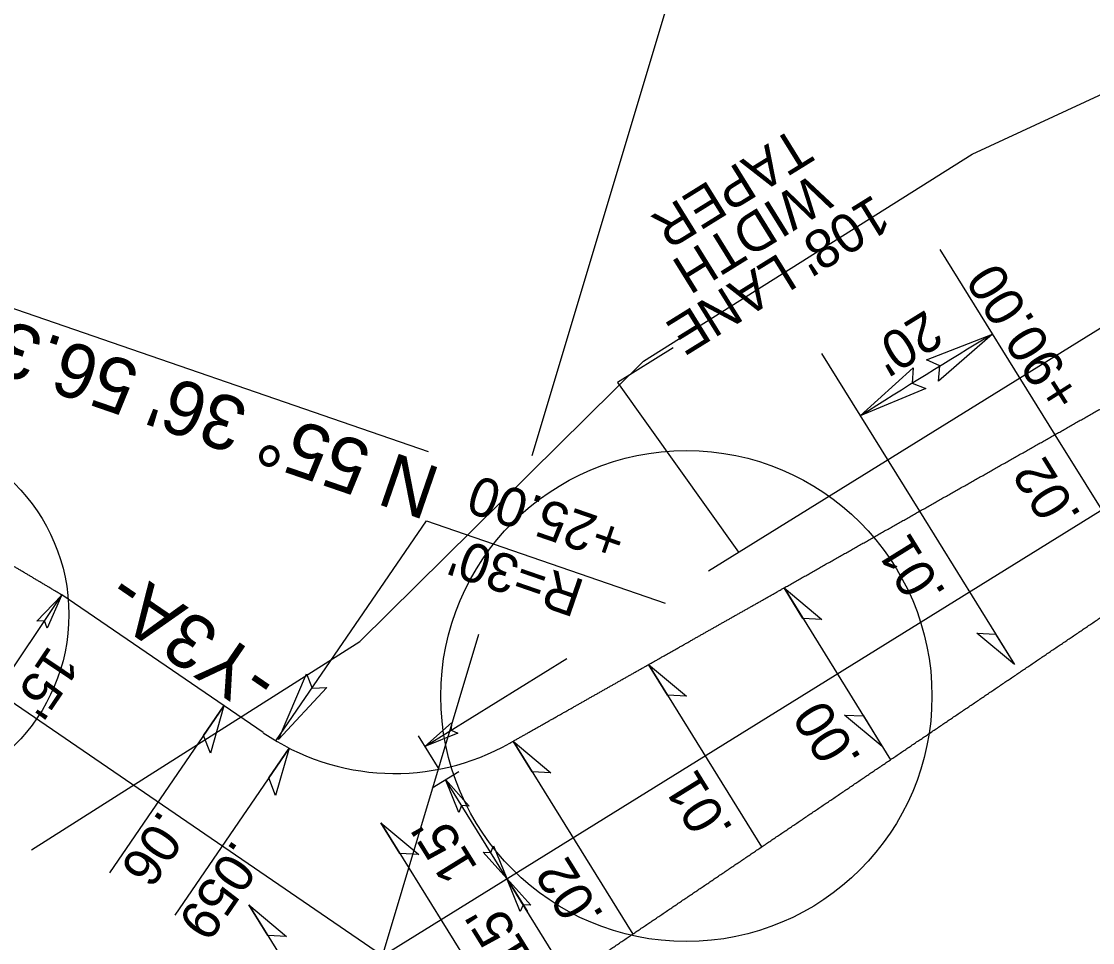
# Model space of a CAD drawing. Extents: x 472216 to 481979, y 489069 to 507339.
# Drawn here: x 480859.9 to 480997.7, y 493143 to 493261.6 of the extents above; entities that cross this region are included whole.
import ezdxf

# ---------------------------------------------------------------- set-up
doc = ezdxf.new("R2010")
doc.units = 0
for name, color, linetype in [('Old_Level_12', 7, 'Continuous'), ('Prop Drainage Structure Drop Inlet Grate 2 Narrow Slots and Sag Grates 840 24 CELL', 7, 'Continuous'), ('Prop Drainage Structure Drop Inlet Grate 2 Wide Slots and Sag Grates 840 22 Label', 7, 'Continuous'), ('Prop Drainage Structure Outlet Berm Ditch 850 10 CELL', 7, 'Continuous'), ('Prop Drainage Structure Pipe CSP 15in', 7, 'Continuous'), ('Prop Drainage Structure Pipe RCP 24in Class III Label', 7, 'Continuous'), ('Sheet Block Revision CELL', 7, 'Continuous'), ('Sheet North Arrow Point CELL', 7, 'Continuous'), ('Sheet PE Seal Cell', 7, 'Continuous'), ('Sheet Plan And Profile CELL', 7, 'Continuous'), ('Sheet Plot Border Outside CELL', 7, 'Continuous'), ('Sheet Sticker Incomplete CELL', 7, 'Continuous')]:
    doc.layers.add(name, color=color, linetype=linetype)

msp = doc.modelspace()

# ---------------------------------------------------------------- linework, layer by layer
at = {"layer": 'Old_Level_12'}
for p, q in [((480925.63, 493205.7), (480990.42, 493422.17)), ((480912.29, 493206.18), (480836.82, 493232.18)), ((480906.37, 493141.34), (480918.76, 493182.72))]:
    msp.add_line(p, q, dxfattribs=at)
at = {"layer": 'Prop Drainage Structure Drop Inlet Grate 2 Narrow Slots and Sag Grates 840 24 CELL'}
for points in [[(480958.01, 493188.66), (480962.87, 493184.61), (480960.44, 493184.73)], [(480987.65, 493178.8), (480982.79, 493182.85), (480985.22, 493182.73)], [(480940.59, 493178.8), (480945.45, 493174.75), (480943.03, 493174.87)], [(480885.96, 493173.49), (480884.22, 493167.41), (480883.35, 493169.67)], [(480970.65, 493168.26), (480965.79, 493172.31), (480968.22, 493172.19)], [(480923.17, 493168.94), (480928.03, 493164.89), (480925.61, 493165.01)], [(480894.36, 493168.05), (480892.62, 493161.97), (480891.74, 493164.23)], [(480906.16, 493158.42), (480911.02, 493154.37), (480908.6, 493154.49)], [(480889.16, 493147.88), (480894.03, 493143.83), (480891.6, 493143.95)]]:
    msp.add_lwpolyline(points, close=True, dxfattribs=at)
at = {"layer": 'Prop Drainage Structure Drop Inlet Grate 2 Wide Slots and Sag Grates 840 22 Label'}
for p, q in [((480978.07, 493232.2), (480992.85, 493208.38)), ((480962.85, 493218.81), (480975.43, 493198.52)), ((480992.85, 493208.38), (481004.65, 493189.34)), ((480975.43, 493198.52), (480987.65, 493178.8)), ((480958.01, 493188.66), (480971.71, 493166.56)), ((480940.59, 493178.8), (480955.13, 493155.34)), ((480885.96, 493173.49), (480871.25, 493152)), ((480923.17, 493168.94), (480938.56, 493144.12)), ((480894.36, 493168.05), (480879.65, 493146.56)), ((480906.16, 493158.42), (480922.4, 493132.23)), ((480889.16, 493147.88), (480910.37, 493113.67))]:
    msp.add_line(p, q, dxfattribs=at)
for points in [[(480976.32, 493217.99), (480984.83, 493221.31), (480977.9, 493215.26), (480978.06, 493217.23)], [(480976.24, 493214.31), (480967.82, 493210.79), (480974.6, 493217), (480974.48, 493215.03)]]:
    msp.add_lwpolyline(points, close=True, dxfattribs=at)
msp.add_arc((481454.86, 492442.1), 910, 121.09915, 122.35843, dxfattribs=at)
at = {"layer": 'Prop Drainage Structure Outlet Berm Ditch 850 10 CELL'}
for points in [[(480861.92, 493184.39), (480865.07, 493187.7), (480863.21, 493183.49), (480862.87, 493184.42)], [(480899.2, 493175.85), (480892.99, 493169.15), (480896.59, 493177.61), (480897.3, 493175.78)], [(480916.06, 493169.97), (480911.82, 493168.26), (480915.25, 493171.32), (480915.18, 493170.34)], [(480916.17, 493159.78), (480914.46, 493164.01), (480917.52, 493160.58), (480916.54, 493160.65)], [(480920.65, 493155.49), (480922.36, 493151.26), (480919.3, 493154.68), (480920.28, 493154.62)], [(480924.08, 493147.03), (480922.36, 493151.26), (480925.43, 493147.84), (480924.45, 493147.9)]]:
    msp.add_lwpolyline(points, close=True, dxfattribs=at)
at = {"layer": 'Prop Drainage Structure Pipe RCP 24in Class III Label'}
msp.add_line((480891.01, 493170.04), (480865.11, 493187.76), dxfattribs=at)
msp.add_arc((480907.95, 493194.79), 30, 235.6156, 299.5114, dxfattribs=at)
for points in [[(480865.11, 493187.76), (480864.91, 493187.87), (480864.72, 493187.99), (480864.53, 493188.1), (480864.33, 493188.22), (480864.14, 493188.33), (480863.95, 493188.45), (480863.75, 493188.57), (480863.56, 493188.68), (480863.37, 493188.8), (480863.17, 493188.91), (480862.98, 493189.03), (480862.78, 493189.14), (480862.59, 493189.26), (480862.4, 493189.37), (480862.2, 493189.49), (480862.01, 493189.61), (480861.82, 493189.72), (480861.62, 493189.84), (480861.43, 493189.95), (480861.24, 493190.07), (480861.04, 493190.18), (480860.85, 493190.3), (480860.65, 493190.41), (480860.46, 493190.53), (480860.27, 493190.65), (480860.07, 493190.76), (480859.88, 493190.88), (480859.69, 493190.99), (480859.49, 493191.11), (480859.3, 493191.22), (480859.1, 493191.34), (480858.91, 493191.45), (480858.72, 493191.57), (480858.52, 493191.69), (480858.33, 493191.8), (480858.14, 493191.92), (480857.94, 493192.03), (480857.75, 493192.15), (480857.56, 493192.26), (480857.36, 493192.38), (480857.17, 493192.49), (480856.97, 493192.61), (480856.78, 493192.73), (480856.59, 493192.84), (480856.39, 493192.96), (480856.2, 493193.07), (480856.01, 493193.19), (480855.81, 493193.3), (480855.62, 493193.42), (480855.43, 493193.53), (480855.23, 493193.65), (480855.04, 493193.77), (480854.84, 493193.88), (480854.65, 493194), (480854.46, 493194.11), (480854.26, 493194.23), (480854.07, 493194.34), (480853.88, 493194.46), (480853.68, 493194.57), (480853.49, 493194.69), (480853.3, 493194.8), (480853.1, 493194.92), (480852.91, 493195.04), (480852.71, 493195.15), (480852.52, 493195.27), (480852.33, 493195.38), (480852.13, 493195.5), (480851.94, 493195.61), (480851.75, 493195.73), (480851.55, 493195.84), (480851.36, 493195.96), (480851.16, 493196.08), (480850.97, 493196.19), (480850.78, 493196.31), (480850.58, 493196.42), (480850.39, 493196.54), (480850.2, 493196.65), (480850, 493196.77), (480849.81, 493196.88), (480849.62, 493197), (480849.42, 493197.12), (480849.23, 493197.23), (480849.03, 493197.35), (480848.84, 493197.46), (480848.65, 493197.58), (480848.45, 493197.69), (480848.26, 493197.81), (480848.07, 493197.92), (480847.87, 493198.04), (480847.68, 493198.16), (480847.49, 493198.27), (480847.29, 493198.39), (480847.1, 493198.5), (480846.9, 493198.62), (480846.71, 493198.73), (480846.52, 493198.85), (480846.32, 493198.96), (480846.13, 493199.08), (480845.94, 493199.2), (480845.74, 493199.31), (480845.55, 493199.43), (480845.35, 493199.54), (480845.16, 493199.66), (480844.97, 493199.77), (480844.77, 493199.89), (480844.58, 493200), (480844.39, 493200.12), (480844.19, 493200.24), (480844, 493200.35), (480843.81, 493200.47), (480843.61, 493200.58), (480843.42, 493200.7), (480843.22, 493200.81), (480843.03, 493200.93), (480842.84, 493201.04), (480842.64, 493201.16), (480842.45, 493201.27), (480842.26, 493201.39), (480842.06, 493201.51), (480841.87, 493201.62), (480841.68, 493201.74), (480841.48, 493201.85), (480841.29, 493201.97), (480841.09, 493202.08), (480840.9, 493202.2), (480840.71, 493202.31), (480840.51, 493202.43), (480840.32, 493202.55), (480840.13, 493202.66), (480839.93, 493202.78), (480839.74, 493202.89), (480839.55, 493203.01), (480839.35, 493203.12), (480839.16, 493203.24), (480838.96, 493203.35), (480838.77, 493203.47), (480838.58, 493203.59), (480838.38, 493203.7), (480838.19, 493203.82), (480838, 493203.93), (480837.8, 493204.05), (480837.61, 493204.16), (480837.41, 493204.28), (480837.22, 493204.39), (480837.03, 493204.51), (480836.83, 493204.63), (480836.64, 493204.74), (480836.47, 493204.84), (480836.29, 493204.95), (480836.12, 493205.05), (480835.96, 493205.15), (480835.79, 493205.24), (480835.63, 493205.34), (480835.47, 493205.44), (480835.31, 493205.53), (480835.15, 493205.63), (480834.99, 493205.73), (480834.83, 493205.83), (480834.67, 493205.93), (480834.51, 493206.03), (480834.35, 493206.13), (480834.19, 493206.23), (480834.03, 493206.33), (480833.87, 493206.43), (480833.72, 493206.54), (480833.56, 493206.64), (480833.4, 493206.74), (480833.24, 493206.85), (480833.09, 493206.95), (480832.93, 493207.06), (480832.77, 493207.16), (480832.62, 493207.27), (480832.46, 493207.37), (480832.3, 493207.48), (480832.15, 493207.59), (480831.99, 493207.69), (480831.84, 493207.8), (480831.68, 493207.91), (480831.53, 493208.02), (480831.37, 493208.13), (480831.22, 493208.24), (480831.07, 493208.35), (480830.91, 493208.46), (480830.76, 493208.57), (480830.61, 493208.68), (480830.45, 493208.79), (480830.3, 493208.91), (480830.15, 493209.02), (480830, 493209.13), (480829.85, 493209.25), (480829.7, 493209.36), (480829.55, 493209.47), (480829.4, 493209.59), (480829.24, 493209.71), (480829.1, 493209.82), (480828.95, 493209.94), (480828.8, 493210.05), (480828.65, 493210.17), (480828.5, 493210.29), (480828.35, 493210.41), (480828.2, 493210.53), (480828.05, 493210.65), (480827.91, 493210.77), (480827.76, 493210.89), (480827.61, 493211.01), (480827.47, 493211.13), (480827.32, 493211.25), (480827.18, 493211.37), (480827.03, 493211.49), (480826.89, 493211.61), (480826.74, 493211.74), (480826.6, 493211.86), (480826.45, 493211.98), (480826.31, 493212.11), (480826.16, 493212.23), (480826.02, 493212.36), (480825.88, 493212.48), (480825.73, 493212.61), (480825.59, 493212.74), (480825.45, 493212.86), (480825.31, 493212.99), (480825.17, 493213.12)], [(480922.73, 493168.69), (480922.91, 493168.79), (480923.1, 493168.9), (480923.29, 493169.01), (480923.48, 493169.12), (480923.68, 493169.23), (480923.88, 493169.34), (480924.07, 493169.45), (480924.27, 493169.56), (480924.46, 493169.67), (480924.66, 493169.78), (480924.86, 493169.89), (480925.05, 493170), (480925.25, 493170.12), (480925.44, 493170.23), (480925.64, 493170.34), (480925.84, 493170.45), (480926.03, 493170.56), (480926.23, 493170.67), (480926.43, 493170.78), (480926.62, 493170.89), (480926.82, 493171), (480927.01, 493171.11), (480927.21, 493171.23), (480927.41, 493171.34), (480927.6, 493171.45), (480927.8, 493171.56), (480927.99, 493171.67), (480928.19, 493171.78), (480928.39, 493171.89), (480928.58, 493172), (480928.78, 493172.11), (480928.98, 493172.23), (480929.17, 493172.34), (480929.37, 493172.45), (480929.56, 493172.56), (480929.76, 493172.67), (480929.96, 493172.78), (480930.15, 493172.89), (480930.35, 493173), (480930.54, 493173.11), (480930.74, 493173.22), (480930.94, 493173.34), (480931.13, 493173.45), (480931.33, 493173.56), (480931.53, 493173.67), (480931.72, 493173.78), (480931.92, 493173.89), (480932.11, 493174), (480932.31, 493174.11), (480932.51, 493174.22), (480932.7, 493174.33), (480932.9, 493174.45), (480933.09, 493174.56), (480933.29, 493174.67), (480933.49, 493174.78), (480933.68, 493174.89), (480933.88, 493175), (480934.08, 493175.11), (480934.27, 493175.22), (480934.47, 493175.33), (480934.66, 493175.45), (480934.86, 493175.56), (480935.06, 493175.67), (480935.25, 493175.78), (480935.45, 493175.89), (480935.64, 493176), (480935.84, 493176.11), (480936.04, 493176.22), (480936.23, 493176.33), (480936.43, 493176.44), (480936.63, 493176.56), (480936.82, 493176.67), (480937.02, 493176.78), (480937.21, 493176.89), (480937.41, 493177), (480937.61, 493177.11), (480937.8, 493177.22), (480938, 493177.33), (480938.19, 493177.44), (480938.39, 493177.55), (480938.59, 493177.67), (480938.78, 493177.78), (480938.98, 493177.89), (480939.18, 493178), (480939.37, 493178.11), (480939.57, 493178.22), (480939.76, 493178.33), (480939.96, 493178.44), (480940.16, 493178.55), (480940.35, 493178.67), (480940.55, 493178.78), (480940.75, 493178.89), (480940.94, 493179), (480941.14, 493179.11), (480941.33, 493179.22), (480941.53, 493179.33), (480941.73, 493179.44), (480941.92, 493179.55), (480942.12, 493179.66), (480942.31, 493179.78), (480942.51, 493179.89), (480942.71, 493180), (480942.9, 493180.11), (480943.1, 493180.22), (480943.3, 493180.33), (480943.49, 493180.44), (480943.69, 493180.55), (480943.88, 493180.66), (480944.08, 493180.77), (480944.28, 493180.89), (480944.47, 493181), (480944.67, 493181.11), (480944.86, 493181.22), (480945.06, 493181.33), (480945.26, 493181.44), (480945.45, 493181.55), (480945.65, 493181.66), (480945.85, 493181.77), (480946.04, 493181.89), (480946.24, 493182), (480946.43, 493182.11), (480946.63, 493182.22), (480946.83, 493182.33), (480947.02, 493182.44), (480947.22, 493182.55), (480947.41, 493182.66), (480947.61, 493182.77), (480947.81, 493182.88), (480948, 493183), (480948.2, 493183.11), (480948.4, 493183.22), (480948.59, 493183.33), (480948.79, 493183.44), (480948.98, 493183.55), (480949.18, 493183.66), (480949.38, 493183.77), (480949.57, 493183.88), (480949.77, 493183.99), (480949.96, 493184.11), (480950.16, 493184.22), (480950.36, 493184.33), (480950.55, 493184.44), (480950.75, 493184.55), (480950.95, 493184.66), (480951.14, 493184.77), (480951.34, 493184.88), (480951.53, 493184.99), (480951.73, 493185.11), (480951.93, 493185.22), (480952.12, 493185.33), (480952.32, 493185.44), (480952.51, 493185.55), (480952.71, 493185.66), (480952.91, 493185.77), (480953.1, 493185.88), (480953.3, 493185.99), (480953.5, 493186.1), (480953.69, 493186.22), (480953.89, 493186.33), (480954.08, 493186.44), (480954.28, 493186.55), (480954.48, 493186.66), (480954.67, 493186.77), (480954.87, 493186.88), (480955.06, 493186.99), (480955.26, 493187.1), (480955.46, 493187.21), (480955.65, 493187.33), (480955.85, 493187.44), (480956.05, 493187.55), (480956.24, 493187.66), (480956.44, 493187.77), (480956.63, 493187.88), (480956.83, 493187.99), (480957.03, 493188.1), (480957.22, 493188.21), (480957.42, 493188.33), (480957.61, 493188.44), (480957.81, 493188.55), (480958.01, 493188.66)]]:
    msp.add_open_spline(points, degree=3, dxfattribs=at)
for points in [[(480958.01, 493188.66), (480958.6, 493188.99), (480959.18, 493189.32), (480959.77, 493189.66), (480960.36, 493189.99), (480960.95, 493190.32), (480961.54, 493190.66), (480962.13, 493190.99), (480962.72, 493191.32), (480963.3, 493191.66), (480963.89, 493191.99), (480964.48, 493192.32), (480965.07, 493192.66), (480965.66, 493192.99), (480966.25, 493193.32), (480966.83, 493193.65), (480967.42, 493193.99), (480968.01, 493194.32), (480968.6, 493194.65), (480969.19, 493194.99), (480969.78, 493195.32), (480970.37, 493195.65), (480970.95, 493195.99), (480971.54, 493196.32), (480972.13, 493196.65), (480972.72, 493196.99), (480973.31, 493197.32), (480973.9, 493197.65), (480974.48, 493197.99), (480975.07, 493198.32), (480975.66, 493198.65), (480976.25, 493198.98), (480976.84, 493199.32), (480977.43, 493199.65), (480978.02, 493199.98), (480978.6, 493200.32), (480979.19, 493200.65), (480979.78, 493200.98), (480980.37, 493201.32), (480980.96, 493201.65), (480981.55, 493201.98), (480982.13, 493202.32), (480982.72, 493202.65), (480983.31, 493202.98), (480983.9, 493203.31), (480984.49, 493203.65), (480985.08, 493203.98), (480985.67, 493204.31), (480986.25, 493204.65), (480986.84, 493204.98), (480987.43, 493205.31), (480988.02, 493205.65), (480988.61, 493205.98), (480989.2, 493206.31), (480989.79, 493206.65), (480990.37, 493206.98), (480990.96, 493207.31), (480991.55, 493207.65), (480992.14, 493207.98), (480992.73, 493208.31), (480993.32, 493208.64), (480993.9, 493208.98), (480994.49, 493209.31), (480995.08, 493209.64), (480995.67, 493209.98), (480996.26, 493210.31), (480996.85, 493210.64), (480997.44, 493210.98), (480998.02, 493211.31), (480998.61, 493211.64), (480999.2, 493211.98), (480999.79, 493212.31), (481000.38, 493212.64), (481001.55, 493213.31)], [(480971.71, 493166.56), (480972.27, 493166.94), (480972.83, 493167.32), (480973.39, 493167.7), (480973.95, 493168.08), (480974.51, 493168.46), (480975.07, 493168.84), (480975.63, 493169.21), (480976.19, 493169.59), (480976.75, 493169.97), (480977.31, 493170.35), (480977.87, 493170.73), (480978.43, 493171.11), (480978.99, 493171.49), (480979.55, 493171.87), (480980.11, 493172.25), (480980.67, 493172.63), (480981.23, 493173.01), (480981.79, 493173.38), (480982.35, 493173.76), (480982.91, 493174.14), (480983.47, 493174.52), (480984.03, 493174.9), (480984.59, 493175.28), (480985.15, 493175.66), (480985.71, 493176.04), (480986.27, 493176.42), (480986.83, 493176.8), (480987.39, 493177.17), (480987.95, 493177.55), (480988.51, 493177.93), (480989.07, 493178.31), (480989.63, 493178.69), (480990.19, 493179.07), (480990.75, 493179.45), (480991.31, 493179.83), (480991.87, 493180.21), (480992.43, 493180.59), (480992.99, 493180.97), (480993.55, 493181.34), (480994.11, 493181.72), (480994.67, 493182.1), (480995.23, 493182.48), (480995.79, 493182.86), (480996.35, 493183.24), (480996.91, 493183.62), (480997.47, 493184), (480998.03, 493184.38), (480998.59, 493184.76), (480999.15, 493185.13), (480999.71, 493185.51), (481000.27, 493185.89), (481000.83, 493186.27), (481001.39, 493186.65), (481001.95, 493187.03), (481002.51, 493187.41), (481003.07, 493187.79), (481003.63, 493188.17), (481004.19, 493188.55), (481004.75, 493188.92), (481005.31, 493189.3), (481005.87, 493189.68), (481006.43, 493190.06), (481006.99, 493190.44), (481007.55, 493190.82), (481008.11, 493191.2), (481008.67, 493191.58), (481009.23, 493191.96), (481009.79, 493192.34), (481010.35, 493192.72), (481010.91, 493193.09), (481011.47, 493193.47), (481012.03, 493193.85), (481013.15, 493194.61)], [(480930.27, 493138.51), (480930.83, 493138.89), (480931.39, 493139.27), (480931.95, 493139.65), (480932.51, 493140.03), (480933.07, 493140.41), (480933.63, 493140.79), (480934.19, 493141.17), (480934.75, 493141.54), (480935.31, 493141.92), (480935.87, 493142.3), (480936.43, 493142.68), (480936.99, 493143.06), (480937.55, 493143.44), (480938.11, 493143.82), (480938.67, 493144.2), (480939.23, 493144.58), (480939.79, 493144.96), (480940.35, 493145.34), (480940.91, 493145.71), (480941.47, 493146.09), (480942.03, 493146.47), (480942.59, 493146.85), (480943.15, 493147.23), (480943.71, 493147.61), (480944.27, 493147.99), (480944.83, 493148.37), (480945.39, 493148.75), (480945.95, 493149.13), (480946.51, 493149.5), (480947.07, 493149.88), (480947.63, 493150.26), (480948.19, 493150.64), (480948.75, 493151.02), (480949.31, 493151.4), (480949.87, 493151.78), (480950.43, 493152.16), (480950.99, 493152.54), (480951.55, 493152.92), (480952.11, 493153.29), (480952.67, 493153.67), (480953.23, 493154.05), (480953.79, 493154.43), (480954.35, 493154.81), (480954.91, 493155.19), (480955.47, 493155.57), (480956.03, 493155.95), (480956.59, 493156.33), (480957.15, 493156.71), (480957.71, 493157.09), (480958.27, 493157.46), (480958.83, 493157.84), (480959.39, 493158.22), (480959.95, 493158.6), (480960.51, 493158.98), (480961.07, 493159.36), (480961.63, 493159.74), (480962.19, 493160.12), (480962.75, 493160.5), (480963.31, 493160.88), (480963.87, 493161.25), (480964.43, 493161.63), (480964.99, 493162.01), (480965.55, 493162.39), (480966.11, 493162.77), (480966.67, 493163.15), (480967.23, 493163.53), (480967.79, 493163.91), (480968.35, 493164.29), (480968.91, 493164.67), (480969.47, 493165.05), (480970.03, 493165.42), (480970.59, 493165.8), (480971.15, 493166.18), (480971.71, 493166.56)]]:
    msp.add_spline(points, degree=3, dxfattribs=at)
at = {"layer": 'Sheet Block Revision CELL'}
for p, q in [((480948.3, 493190.87), (481003.61, 493225.17)), ((480943.76, 493219.54), (480936.61, 493215.11)), ((480936.61, 493215.11), (480952.17, 493193.27)), ((480892.65, 493168.99), (480912.02, 493197.28)), ((480912.02, 493197.28), (480942.7, 493186.71)), ((480848.39, 493162.85), (480865.07, 493187.7)), ((480911.82, 493168.26), (480930.06, 493179.57)), ((480910.97, 493169.64), (480913.63, 493165.34)), ((480912.76, 493162.95), (480916.16, 493165.06)), ((480930.27, 493138.51), (480914.46, 493164.01)), ((480929.7, 493139.43), (480914.46, 493164.01))]:
    msp.add_line(p, q, dxfattribs=at)
at = {"layer": 'Sheet North Arrow Point CELL'}
for p, q in [((480837.38, 493098.56), (481302.46, 493386.95)), ((480906.37, 493141.34), (480828.13, 493194.89))]:
    msp.add_line(p, q, dxfattribs=at)
msp.add_arc((480155.89, 492286.67), 1060, 12.98112, 71.78843, dxfattribs=at)
msp.add_arc((480155.89, 492286.67), 1060, 12.98112, 71.78843, dxfattribs=at)
at = {"layer": 'Sheet PE Seal Cell'}
for p, q in [((480922.36, 493151.26), (480925, 493147.01)), ((480925, 493147.01), (480922.36, 493151.26))]:
    msp.add_line(p, q, dxfattribs=at)
at = {"layer": 'Sheet Plot Border Outside CELL'}
for centre, radius in [((480842.21, 493185.25), 23.81), ((480945.45, 493174.75), 31.59)]:
    msp.add_circle(centre, radius, dxfattribs=at)
at = {"layer": 'Sheet Sticker Incomplete CELL'}
for p, q in [((480982.22, 493244.48), (481027.91, 493265.68)), ((480939.92, 493217.83), (480982.22, 493244.48)), ((480903.44, 493181.78), (480939.92, 493217.83)), ((480861.23, 493154.97), (480903.44, 493181.78))]:
    msp.add_line(p, q, dxfattribs=at)

# ---------------------------------------------------------------- texts
at = {"layer": 'Prop Drainage Structure Drop Inlet Grate 2 Narrow Slots and Sag Grates 840 24 CELL'}
for s, rotation, p in [('.02', 121.8022, (480996.34, 493197.98)), ('.01', 121.8022, (480978.96, 493188.05)), ('.00', 121.8022, (480968.06, 493166.71)), ('.01', 121.8022, (480951.57, 493157.65)), ('.06', 235.6156, (480877.76, 493160.3)), ('.059', 235.6156, (480887.26, 493156.47)), ('.02', 121.8022, (480934.95, 493146.5))]:
    msp.add_text(s, height=5, rotation=rotation, dxfattribs=at).set_placement(p)
at = {"layer": 'Prop Drainage Structure Drop Inlet Grate 2 Wide Slots and Sag Grates 840 22 Label'}
for s, rotation, p in [('+90.00', 122.4459, (480996.5, 493213.46)), ("20'", 211.7674, (480976.3, 493224.54))]:
    msp.add_text(s, height=5, rotation=rotation, dxfattribs=at).set_placement(p)
at = {"layer": 'Prop Drainage Structure Pipe CSP 15in'}
for s, rotation, p in [('TAPER', 211.8022, (480959.48, 493248.06)), ('WIDTH ', 211.8022, (480961.9, 493242.1)), ("108' LANE ", 211.8022, (480969.56, 493239.39)), ('+25.00', 160.9892, (480938.01, 493196.54)), ("R=30'", 160.9892, (480932.6, 493189.55)), ("15'", 236.0987, (480863.51, 493181.43)), ("15'", 121.8022, (480918.71, 493152.65)), ("15'", 121.8022, (480925.66, 493141.4))]:
    msp.add_text(s, height=5, rotation=rotation, dxfattribs=at).set_placement(p)
at = {"layer": 'Sheet Plan And Profile CELL'}
for s, rotation, p in [('N 55%%d 36\' 56.3" W', 160.9892, (480914.12, 493203.96)), ('-Y3A-', 145.6156, (480893.49, 493177.88))]:
    msp.add_text(s, height=7, rotation=rotation, dxfattribs=at).set_placement(p)

doc.saveas('drawing.dxf')
